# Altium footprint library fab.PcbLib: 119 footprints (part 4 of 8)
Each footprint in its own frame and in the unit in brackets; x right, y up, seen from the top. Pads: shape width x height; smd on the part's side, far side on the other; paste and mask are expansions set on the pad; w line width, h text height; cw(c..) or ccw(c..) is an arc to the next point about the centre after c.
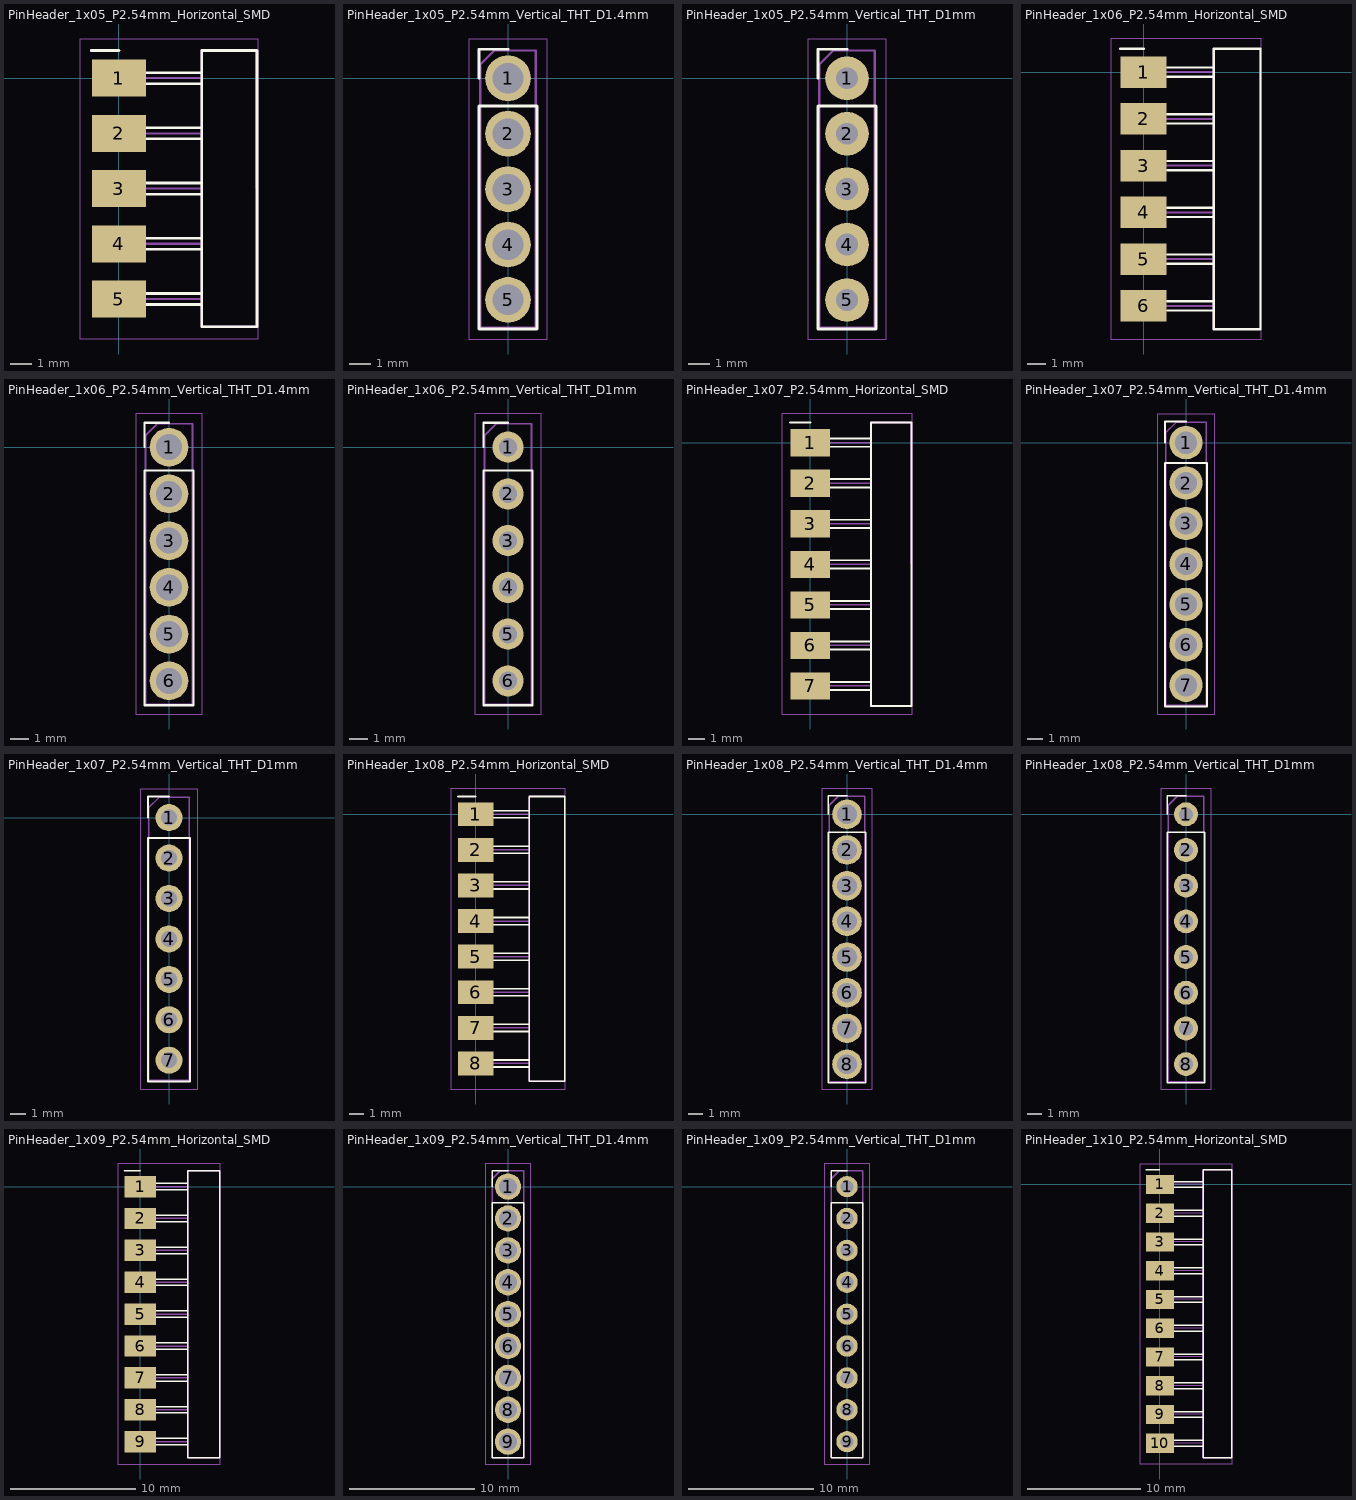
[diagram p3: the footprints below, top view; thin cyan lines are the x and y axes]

## PinHeader_1x05_P2.54mm_Horizontal_SMD [mm]
pads (5):
  rect 2.5x1.7 smd: 1(0,0) 2(0,-2.54) 3(0,-5.08) 4(0,-7.62) 5(0,-10.16)
F.SilkS:
  lines w0.12: -1.27,1.27 0,1.27 ; 1.27,-10.414 3.81,-10.414 ; 1.27,-9.906 3.81,-9.906 ; 1.27,-7.874 3.81,-7.874 ; 1.27,-7.366 3.81,-7.366 ; 1.27,-5.334 3.81,-5.334 ; 1.27,-4.826 3.81,-4.826 ; 1.27,-2.794 3.81,-2.794 ; 1.27,-2.286 3.81,-2.286 ; 1.27,-0.254 3.81,-0.254 ; 1.27,0.254 3.81,0.254 ; 3.81,-11.43 3.81,1.27 6.35,1.27 6.35,-11.43 3.81,-11.43
F.CrtYd:
  lines w0.05: -1.8,-12 -1.8,1.8 6.4,1.8 6.4,-12 -1.8,-12
F.Fab:
  lines w0.1: -0.635,-10.414 -0.635,-9.906 ; -0.635,-10.16 3.81,-10.16 ; -0.635,-7.874 -0.635,-7.366 ; -0.635,-7.62 3.81,-7.62 ; -0.635,-5.334 -0.635,-4.826 ; -0.635,-5.08 3.81,-5.08 ; -0.635,-2.794 -0.635,-2.286 ; -0.635,-2.54 3.81,-2.54 ; -0.635,-0.254 -0.635,0.254 ; -0.635,0 3.81,0 ; 3.8,-11.43 6.35,-11.43 6.34,1.27 3.8,1.27 3.81,-11.43
  text "%R" at 2.834,-5.473 h1

## PinHeader_1x05_P2.54mm_Vertical_THT_D1.4mm [mm]
pads (5):
  round 2.1 hole 1.4: 1(0,0) 2(0,-2.54) 3(0,-5.08) 4(0,-7.62) 5(0,-10.16)
F.SilkS:
  lines w0.12: -1.33,0 -1.33,1.33 0,1.33 ; -1.33,-11.49 1.33,-11.49 1.33,-1.27 -1.33,-1.27 -1.33,-11.49
F.CrtYd:
  lines w0.05: -1.8,-11.95 -1.8,1.8 1.8,1.8 1.8,-11.95 -1.8,-11.95
F.Fab:
  lines w0.1: -1.27,-11.43 1.27,-11.43 1.27,1.27 -0.635,1.27 -1.27,0.635 -1.27,-11.43
  text "%R" at 0.294,-5.473 h1

## PinHeader_1x05_P2.54mm_Vertical_THT_D1mm [mm]
pads (5):
  round 2 hole 1: 1(0,0)
  rrect100% 2x2 hole 1: 2(0,-2.54) 3(0,-5.08) 4(0,-7.62) 5(0,-10.16)
F.SilkS:
  lines w0.12: -1.33,0 -1.33,1.33 0,1.33 ; -1.33,-11.49 -1.33,-1.27 1.33,-1.27 1.33,-11.49 -1.33,-11.49
F.CrtYd:
  lines w0.05: -1.8,-11.95 1.8,-11.95 1.8,1.8 -1.8,1.8 -1.8,-11.95
F.Fab:
  lines w0.1: -1.27,-11.43 -1.27,0.635 -0.635,1.27 1.27,1.27 1.27,-11.43 -1.27,-11.43
  text "%R" at 0.294,-5.473 h1

## PinHeader_1x06_P2.54mm_Horizontal_SMD [mm]
pads (6):
  rect 2.5x1.7 smd: 1(0,0) 2(0,-2.54) 3(0,-5.08) 4(0,-7.62) 5(0,-10.16) 6(0,-12.7)
F.SilkS:
  lines w0.12: -1.27,1.27 0,1.27 ; 1.27,-12.954 3.81,-12.954 ; 1.27,-12.446 3.81,-12.446 ; 1.27,-10.414 3.81,-10.414 ; 1.27,-9.906 3.81,-9.906 ; 1.27,-7.874 3.81,-7.874 ; 1.27,-7.366 3.81,-7.366 ; 1.27,-5.334 3.81,-5.334 ; 1.27,-4.826 3.81,-4.826 ; 1.27,-2.794 3.81,-2.794 ; 1.27,-2.286 3.81,-2.286 ; 1.27,-0.254 3.81,-0.254 ; 1.27,0.254 3.81,0.254 ; 3.81,-13.97 3.81,1.27 6.35,1.27 6.35,-13.97 3.81,-13.97
F.CrtYd:
  lines w0.05: -1.8,-14.5 -1.8,1.8 6.4,1.8 6.4,-14.5 -1.8,-14.5
F.Fab:
  lines w0.1: -0.635,-12.954 -0.635,-12.446 ; -0.635,-12.7 3.81,-12.7 ; -0.635,-10.414 -0.635,-9.906 ; -0.635,-10.16 3.81,-10.16 ; -0.635,-7.874 -0.635,-7.366 ; -0.635,-7.62 3.81,-7.62 ; -0.635,-5.334 -0.635,-4.826 ; -0.635,-5.08 3.81,-5.08 ; -0.635,-2.794 -0.635,-2.286 ; -0.635,-2.54 3.81,-2.54 ; -0.635,-0.254 -0.635,0.254 ; -0.635,0 3.81,0 ; 3.8,-13.97 6.35,-13.97 6.34,1.27 3.8,1.27 3.8,-13.97
  text "%R" at 2.894,-6.493 h1

## PinHeader_1x06_P2.54mm_Vertical_THT_D1.4mm [mm]
pads (6):
  round 2.1 hole 1.4: 1(0,0) 2(0,-2.54) 3(0,-5.08) 4(0,-7.62) 5(0,-10.16) 6(0,-12.7)
F.SilkS:
  lines w0.12: -1.33,0 -1.33,1.33 0,1.33 ; -1.33,-14.03 -1.33,-1.27 1.33,-1.27 1.33,-14.03 -1.33,-14.03
F.CrtYd:
  lines w0.05: -1.8,-14.5 1.8,-14.5 1.8,1.8 -1.8,1.8 -1.8,-14.5
F.Fab:
  lines w0.1: -1.27,-13.97 -1.27,0.635 -0.635,1.27 1.27,1.27 1.27,-13.97 -1.27,-13.97
  text "%R" at 0.294,-6.743 h1

## PinHeader_1x06_P2.54mm_Vertical_THT_D1mm [mm]
pads (6):
  round 1.7 hole 1: 1(0,0)
  rrect100% 1.7x1.7 hole 1: 2(0,-2.54) 3(0,-5.08) 4(0,-7.62) 5(0,-10.16) 6(0,-12.7)
F.SilkS:
  lines w0.12: -1.33,0 -1.33,1.33 0,1.33 ; -1.33,-14.03 1.33,-14.03 1.33,-1.27 -1.33,-1.27 -1.33,-14.03
F.CrtYd:
  lines w0.05: -1.8,-14.5 -1.8,1.8 1.8,1.8 1.8,-14.5 -1.8,-14.5
F.Fab:
  lines w0.1: -1.27,-13.97 1.27,-13.97 1.27,1.27 -0.635,1.27 -1.27,0.635 -1.27,-13.97
  text "%R" at 0.294,-6.743 h1

## PinHeader_1x07_P2.54mm_Horizontal_SMD [mm]
pads (7):
  rect 2.5x1.7 smd: 1(0,0) 2(0,-2.54) 3(0,-5.08) 4(0,-7.62) 5(0,-10.16) 6(0,-12.7) 7(0,-15.24)
F.SilkS:
  lines w0.12: -1.27,1.27 0,1.27 ; 1.27,-15.494 3.81,-15.494 ; 1.27,-14.986 3.81,-14.986 ; 1.27,-12.954 3.81,-12.954 ; 1.27,-12.446 3.81,-12.446 ; 1.27,-10.414 3.81,-10.414 ; 1.27,-9.906 3.81,-9.906 ; 1.27,-7.874 3.81,-7.874 ; 1.27,-7.366 3.81,-7.366 ; 1.27,-5.334 3.81,-5.334 ; 1.27,-4.826 3.81,-4.826 ; 1.27,-2.794 3.81,-2.794 ; 1.27,-2.286 3.81,-2.286 ; 1.27,-0.254 3.81,-0.254 ; 1.27,0.254 3.81,0.254 ; 3.81,-16.51 3.81,1.27 6.35,1.27 6.35,-16.51 3.81,-16.51
F.CrtYd:
  lines w0.05: -1.8,-17 -1.8,1.8 6.4,1.8 6.4,-17 -1.8,-17
F.Fab:
  lines w0.1: -0.635,-15.494 -0.635,-14.986 ; -0.635,-15.24 3.81,-15.24 ; -0.635,-12.954 -0.635,-12.446 ; -0.635,-12.7 3.81,-12.7 ; -0.635,-10.414 -0.635,-9.906 ; -0.635,-10.16 3.81,-10.16 ; -0.635,-7.874 -0.635,-7.366 ; -0.635,-7.62 3.81,-7.62 ; -0.635,-5.334 -0.635,-4.826 ; -0.635,-5.08 3.81,-5.08 ; -0.635,-2.794 -0.635,-2.286 ; -0.635,-2.54 3.81,-2.54 ; -0.635,-0.254 -0.635,0.254 ; -0.635,0 3.81,0 ; 3.8,-16.51 6.35,-16.51 6.34,1.27 3.8,1.27 3.8,-16.51
  text "%R" at 2.894,-8.013 h1

## PinHeader_1x07_P2.54mm_Vertical_THT_D1.4mm [mm]
pads (7):
  round 2.1 hole 1.4: 1(0,0) 2(0,-2.54) 3(0,-5.08) 4(0,-7.62) 5(0,-10.16) 6(0,-12.7) 7(0,-15.24)
F.SilkS:
  lines w0.12: -1.33,0 -1.33,1.33 0,1.33 ; -1.33,-16.57 -1.33,-1.27 1.33,-1.27 1.33,-16.57 -1.33,-16.57
F.CrtYd:
  lines w0.05: -1.8,-17.05 1.8,-17.05 1.8,1.8 -1.8,1.8 -1.8,-17.05
F.Fab:
  lines w0.1: -1.27,-16.51 -1.27,0.635 -0.635,1.27 1.27,1.27 1.27,-16.51 -1.27,-16.51
  text "%R" at 0.294,-8.013 h1

## PinHeader_1x07_P2.54mm_Vertical_THT_D1mm [mm]
pads (7):
  round 1.7 hole 1: 1(0,0)
  rrect100% 1.7x1.7 hole 1: 2(0,-2.54) 3(0,-5.08) 4(0,-7.62) 5(0,-10.16) 6(0,-12.7) 7(0,-15.24)
F.SilkS:
  lines w0.12: -1.33,0 -1.33,1.33 0,1.33 ; -1.33,-16.57 1.33,-16.57 1.33,-1.27 -1.33,-1.27 -1.33,-16.57
F.CrtYd:
  lines w0.05: -1.8,-17.05 -1.8,1.8 1.8,1.8 1.8,-17.05 -1.8,-17.05
F.Fab:
  lines w0.1: -1.27,-16.51 1.27,-16.51 1.27,1.27 -0.635,1.27 -1.27,0.635 -1.27,-16.51
  text "%R" at 0.294,-8.013 h1

## PinHeader_1x08_P2.54mm_Horizontal_SMD [mm]
pads (8):
  rect 2.5x1.7 smd: 1(0,0) 2(0,-2.54) 3(0,-5.08) 4(0,-7.62) 5(0,-10.16) 6(0,-12.7) 7(0,-15.24) 8(0,-17.78)
F.SilkS:
  lines w0.12: -1.27,1.27 0,1.27 ; 1.27,-18.034 3.81,-18.034 ; 1.27,-17.526 3.81,-17.526 ; 1.27,-15.494 3.81,-15.494 ; 1.27,-14.986 3.81,-14.986 ; 1.27,-12.954 3.81,-12.954 ; 1.27,-12.446 3.81,-12.446 ; 1.27,-10.414 3.81,-10.414 ; 1.27,-9.906 3.81,-9.906 ; 1.27,-7.874 3.81,-7.874 ; 1.27,-7.366 3.81,-7.366 ; 1.27,-5.334 3.81,-5.334 ; 1.27,-4.826 3.81,-4.826 ; 1.27,-2.794 3.81,-2.794 ; 1.27,-2.286 3.81,-2.286 ; 1.27,-0.254 3.81,-0.254 ; 1.27,0.254 3.81,0.254 ; 3.81,-19.05 6.35,-19.05 6.35,1.27 3.81,1.27 3.81,-19.05
F.CrtYd:
  lines w0.05: -1.8,-19.6 6.4,-19.6 6.4,1.8 -1.8,1.8 -1.8,-19.6
F.Fab:
  lines w0.1: -0.635,-18.034 -0.635,-17.526 ; -0.635,-17.78 3.81,-17.78 ; -0.635,-15.494 -0.635,-14.986 ; -0.635,-15.24 3.81,-15.24 ; -0.635,-12.954 -0.635,-12.446 ; -0.635,-12.7 3.81,-12.7 ; -0.635,-10.414 -0.635,-9.906 ; -0.635,-10.16 3.81,-10.16 ; -0.635,-7.874 -0.635,-7.366 ; -0.635,-7.62 3.81,-7.62 ; -0.635,-5.334 -0.635,-4.826 ; -0.635,-5.08 3.81,-5.08 ; -0.635,-2.794 -0.635,-2.286 ; -0.635,-2.54 3.81,-2.54 ; -0.635,-0.254 -0.635,0.254 ; -0.635,0 3.81,0 ; 3.8,-19.05 3.8,1.27 6.34,1.27 6.35,-19.05 3.8,-19.05
  text "%R" at 2.834,-9.283 h1

## PinHeader_1x08_P2.54mm_Vertical_THT_D1.4mm [mm]
pads (8):
  round 2.1 hole 1.4: 1(0,0) 2(0,-2.54) 3(0,-5.08) 4(0,-7.62) 5(0,-10.16) 6(0,-12.7) 7(0,-15.24) 8(0,-17.78)
F.SilkS:
  lines w0.12: -1.33,0 -1.33,1.33 0,1.33 ; -1.33,-19.11 -1.33,-1.27 1.33,-1.27 1.33,-19.11 -1.33,-19.11
F.CrtYd:
  lines w0.05: -1.8,-19.55 1.8,-19.55 1.8,1.8 -1.8,1.8 -1.8,-19.55
F.Fab:
  lines w0.1: -1.27,-19.05 -1.27,0.635 -0.635,1.27 1.27,1.27 1.27,-19.05 -1.27,-19.05
  text "%R" at 0.294,-9.283 h1

## PinHeader_1x08_P2.54mm_Vertical_THT_D1mm [mm]
pads (8):
  round 1.7 hole 1: 1(0,0)
  rrect100% 1.7x1.7 hole 1: 2(0,-2.54) 3(0,-5.08) 4(0,-7.62) 5(0,-10.16) 6(0,-12.7) 7(0,-15.24) 8(0,-17.78)
F.SilkS:
  lines w0.12: -1.33,0 -1.33,1.33 0,1.33 ; -1.33,-19.11 1.33,-19.11 1.33,-1.27 -1.33,-1.27 -1.33,-19.11
F.CrtYd:
  lines w0.05: -1.8,-19.55 -1.8,1.8 1.8,1.8 1.8,-19.55 -1.8,-19.55
F.Fab:
  lines w0.1: -1.27,-19.05 1.27,-19.05 1.27,1.27 -0.635,1.27 -1.27,0.635 -1.27,-19.05
  text "%R" at 0.294,-9.283 h1

## PinHeader_1x09_P2.54mm_Horizontal_SMD [mm]
pads (9):
  rect 2.5x1.7 smd: 1(0,0) 2(0,-2.54) 3(0,-5.08) 4(0,-7.62) 5(0,-10.16) 6(0,-12.7) 7(0,-15.24) 8(0,-17.78) 9(0,-20.32)
F.SilkS:
  lines w0.12: -1.27,1.27 0,1.27 ; 1.27,-20.574 3.81,-20.574 ; 1.27,-20.066 3.81,-20.066 ; 1.27,-18.034 3.81,-18.034 ; 1.27,-17.526 3.81,-17.526 ; 1.27,-15.494 3.81,-15.494 ; 1.27,-14.986 3.81,-14.986 ; 1.27,-12.954 3.81,-12.954 ; 1.27,-12.446 3.81,-12.446 ; 1.27,-10.414 3.81,-10.414 ; 1.27,-9.906 3.81,-9.906 ; 1.27,-7.874 3.81,-7.874 ; 1.27,-7.366 3.81,-7.366 ; 1.27,-5.334 3.81,-5.334 ; 1.27,-4.826 3.81,-4.826 ; 1.27,-2.794 3.81,-2.794 ; 1.27,-2.286 3.81,-2.286 ; 1.27,-0.254 3.81,-0.254 ; 1.27,0.254 3.81,0.254 ; 3.81,-21.59 6.35,-21.59 6.35,1.27 3.81,1.27 3.81,-21.59
F.CrtYd:
  lines w0.05: -1.8,-22.1 6.4,-22.1 6.4,1.8 -1.8,1.8 -1.8,-22.1
F.Fab:
  lines w0.1: -0.635,-20.574 -0.635,-20.066 ; -0.635,-20.32 3.81,-20.32 ; -0.635,-18.034 -0.635,-17.526 ; -0.635,-17.78 3.81,-17.78 ; -0.635,-15.494 -0.635,-14.986 ; -0.635,-15.24 3.81,-15.24 ; -0.635,-12.954 -0.635,-12.446 ; -0.635,-12.7 3.81,-12.7 ; -0.635,-10.414 -0.635,-9.906 ; -0.635,-10.16 3.81,-10.16 ; -0.635,-7.874 -0.635,-7.366 ; -0.635,-7.62 3.81,-7.62 ; -0.635,-5.334 -0.635,-4.826 ; -0.635,-5.08 3.81,-5.08 ; -0.635,-2.794 -0.635,-2.286 ; -0.635,-2.54 3.81,-2.54 ; -0.635,-0.254 -0.635,0.254 ; -0.635,0 3.81,0 ; 3.8,-21.59 3.8,1.27 6.34,1.27 6.35,-21.59 3.8,-21.59
  text "%R" at 2.834,-10.553 h1

## PinHeader_1x09_P2.54mm_Vertical_THT_D1.4mm [mm]
pads (9):
  round 2.1 hole 1.4: 1(0,0) 2(0,-2.54) 3(0,-5.08) 4(0,-7.62) 5(0,-10.16) 6(0,-12.7) 7(0,-15.24) 8(0,-17.78) 9(0,-20.32)
F.SilkS:
  lines w0.12: -1.27,0 -1.27,1.27 0,1.27 ; -1.27,-21.59 -1.27,-1.27 1.27,-1.27 1.27,-21.59 -1.27,-21.59
F.CrtYd:
  lines w0.05: -1.8,-22.1 1.8,-22.1 1.8,1.8 -1.8,1.8 -1.8,-22.1
F.Fab:
  lines w0.1: -1.27,-21.59 -1.27,0.635 -0.635,1.27 1.27,1.27 1.27,-21.59 -1.27,-21.59
  text "%R" at 0.294,-9.283 h1

## PinHeader_1x09_P2.54mm_Vertical_THT_D1mm [mm]
pads (9):
  round 1.7 hole 1: 1(0,0)
  rrect100% 1.7x1.7 hole 1: 2(0,-2.54) 3(0,-5.08) 4(0,-7.62) 5(0,-10.16) 6(0,-12.7) 7(0,-15.24) 8(0,-17.78) 9(0,-20.32)
F.SilkS:
  lines w0.12: -1.27,0 -1.27,1.27 0,1.27 ; -1.27,-21.59 1.27,-21.59 1.27,-1.27 -1.27,-1.27 -1.27,-21.59
F.CrtYd:
  lines w0.05: -1.8,-22.1 -1.8,1.8 1.8,1.8 1.8,-22.1 -1.8,-22.1
F.Fab:
  lines w0.1: -1.27,-21.59 1.27,-21.59 1.27,1.27 -0.635,1.27 -1.27,0.635 -1.27,-21.59
  text "%R" at 0.294,-9.283 h1

## PinHeader_1x10_P2.54mm_Horizontal_SMD [mm]
pads (10):
  rect 2.5x1.7 smd: 1(0,0) 2(0,-2.54) 3(0,-5.08) 4(0,-7.62) 5(0,-10.16) 6(0,-12.7) 7(0,-15.24) 8(0,-17.78) 9(0,-20.32) 10(0,-22.86)
F.SilkS:
  lines w0.12: -1.27,1.27 0,1.27 ; 1.27,-23.114 3.81,-23.114 ; 1.27,-22.606 3.81,-22.606 ; 1.27,-20.574 3.81,-20.574 ; 1.27,-20.066 3.81,-20.066 ; 1.27,-18.034 3.81,-18.034 ; 1.27,-17.526 3.81,-17.526 ; 1.27,-15.494 3.81,-15.494 ; 1.27,-14.986 3.81,-14.986 ; 1.27,-12.954 3.81,-12.954 ; 1.27,-12.446 3.81,-12.446 ; 1.27,-10.414 3.81,-10.414 ; 1.27,-9.906 3.81,-9.906 ; 1.27,-7.874 3.81,-7.874 ; 1.27,-7.366 3.81,-7.366 ; 1.27,-5.334 3.81,-5.334 ; 1.27,-4.826 3.81,-4.826 ; 1.27,-2.794 3.81,-2.794 ; 1.27,-2.286 3.81,-2.286 ; 1.27,-0.254 3.81,-0.254 ; 1.27,0.254 3.81,0.254 ; 3.81,-24.13 3.81,1.27 6.35,1.27 6.35,-24.13 3.81,-24.13
F.CrtYd:
  lines w0.05: -1.8,-24.7 -1.8,1.8 6.4,1.8 6.4,-24.7 -1.8,-24.7
F.Fab:
  lines w0.1: -0.635,-23.114 -0.635,-22.606 ; -0.635,-22.86 3.81,-22.86 ; -0.635,-20.574 -0.635,-20.066 ; -0.635,-20.32 3.81,-20.32 ; -0.635,-18.034 -0.635,-17.526 ; -0.635,-17.78 3.81,-17.78 ; -0.635,-15.494 -0.635,-14.986 ; -0.635,-15.24 3.81,-15.24 ; -0.635,-12.954 -0.635,-12.446 ; -0.635,-12.7 3.81,-12.7 ; -0.635,-10.414 -0.635,-9.906 ; -0.635,-10.16 3.81,-10.16 ; -0.635,-7.874 -0.635,-7.366 ; -0.635,-7.62 3.81,-7.62 ; -0.635,-5.334 -0.635,-4.826 ; -0.635,-5.08 3.81,-5.08 ; -0.635,-2.794 -0.635,-2.286 ; -0.635,-2.54 3.81,-2.54 ; -0.635,-0.254 -0.635,0.254 ; -0.635,0 3.81,0 ; 3.8,-24.13 6.35,-24.13 6.34,1.27 3.8,1.27 3.8,-24.13
  text "%R" at 2.834,-11.823 h1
